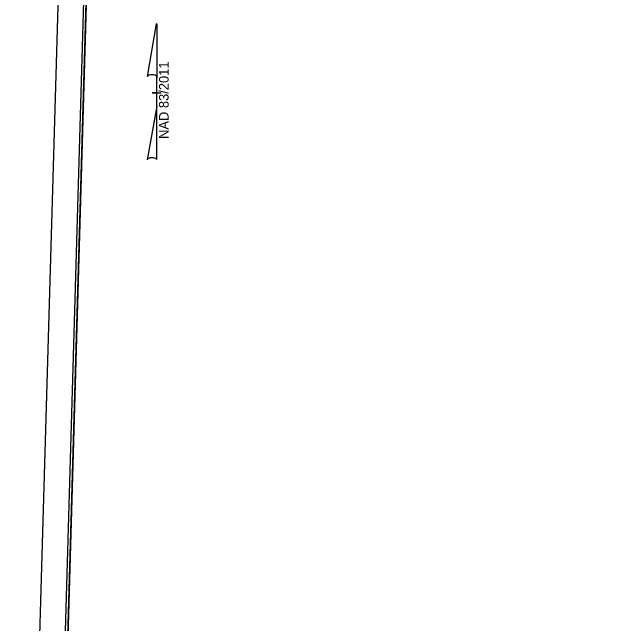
# Model space of a CAD drawing. Extents: x 2097000 to 2098148, y 684979 to 687012.
# Drawn here: x 2097000 to 2097532, y 685995 to 686534 of the extents above; entities that cross this region are included whole.
import ezdxf

# ---------------------------------------------------------------- set-up
doc = ezdxf.new("R2010")
doc.units = 0
for name, color, linetype in [('Prop North Arrow NAD83 for Plan Sheets CELL', 7, 'Continuous'), ('Sheet Layout Plan Border', 7, 'Continuous'), ('Sheet Plot Border Inside CELL', 7, 'Continuous'), ('Sheet Plot Border Outside CELL', 7, 'Continuous'), ('Sheet Profile CELL', 7, 'Continuous')]:
    doc.layers.add(name, color=color, linetype=linetype)

msp = doc.modelspace()

# ---------------------------------------------------------------- linework, layer by layer
at = {"layer": 'Prop North Arrow NAD83 for Plan Sheets CELL'}
for p, q in [((2097118.64, 686477.64), (2097126.84, 686523.99)), ((2097126.89, 686523.99), (2097126.84, 686523.99)), ((2097126.89, 686523.99), (2097126.84, 686523.99)), ((2097126.89, 686523.99), (2097126.89, 686476.19)), ((2097126.89, 686451.39), (2097126.89, 686477.59)), ((2097126.89, 686476.19), (2097126.89, 686477.54)), ((2097122.89, 686462.99), (2097122.84, 686462.99)), ((2097126.44, 686462.99), (2097122.89, 686462.99)), ((2097122.94, 686462.99), (2097130.94, 686462.99)), ((2097126.89, 686451.39), (2097118.54, 686404.14)), ((2097126.94, 686404.34), (2097126.89, 686451.39))]:
    msp.add_line(p, q, dxfattribs=at)
for centre, start_param, end_param in [((2097122.78, 686477.14), 0.216388, 2.908219), ((2097122.78, 686403.97), 0.201328, 3.141593)]:
    msp.add_ellipse(centre, major_axis=(4.23, -0.03), ratio=0.461098, start_param=start_param, end_param=end_param, dxfattribs=at)
at = {"layer": 'Sheet Layout Plan Border'}
msp.add_lwpolyline([(2098090.85, 685704.42), (2097236.93, 685318.96), (2097029.37, 685324.99), (2097067.15, 686624.39), (2097254.37, 686618.95), (2097261.85, 686618.73), (2097260.99, 686589.19), (2097439.33, 686584), (2097443.49, 686726.82), (2098120, 686707.16)], close=True, dxfattribs=at)
at = {"layer": 'Sheet Plot Border Inside CELL'}
msp.add_lwpolyline([(2098077, 685140.47), (2098125.43, 686806.26), (2097070.77, 686836.92), (2097022.35, 685171.13)], close=True, dxfattribs=at)
at = {"layer": 'Sheet Plot Border Outside CELL'}
msp.add_lwpolyline([(2098099.07, 685126.82), (2098148, 686810.11), (2097048.47, 686842.07), (2096999.53, 685158.79)], close=True, dxfattribs=at)
at = {"layer": 'Sheet Profile CELL'}
msp.add_lwpolyline([(2097072.96, 686824.36), (2097029.37, 685324.99), (2098078.93, 685294.48), (2098122.52, 686793.84)], close=True, dxfattribs=at)

# ---------------------------------------------------------------- texts
at = {"layer": 'Prop North Arrow NAD83 for Plan Sheets CELL'}
msp.add_text('NAD 83/2011', height=8.5, rotation=90, dxfattribs=at).set_placement((2097137.41, 686422.51))

doc.saveas('drawing.dxf')
